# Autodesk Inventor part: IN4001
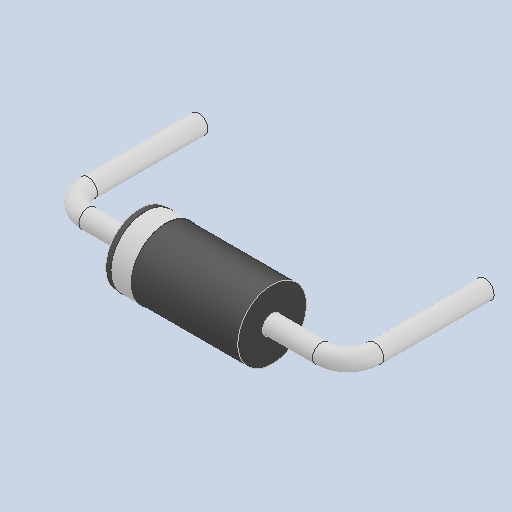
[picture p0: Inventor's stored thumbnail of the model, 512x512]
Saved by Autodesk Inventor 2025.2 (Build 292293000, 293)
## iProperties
Created: 2025-04
Part Number: IN4001
Material: Generic
Description: PART-IN4001-DESC
Document SubType Name: Modeling
Designer: BennF
Density: 1 g/cm^3
Appearance: Default
Author: BennF
Revision Number: NONE
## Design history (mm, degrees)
feature "Solid"
feature "Solid:1"
feature "Solid:2"
body "Solid1"
body "Solid2"
body "Solid3"
